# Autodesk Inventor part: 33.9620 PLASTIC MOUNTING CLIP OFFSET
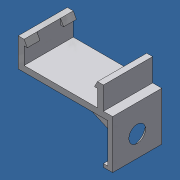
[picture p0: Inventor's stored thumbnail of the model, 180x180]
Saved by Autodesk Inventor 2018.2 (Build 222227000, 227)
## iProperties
Created: 2018-05
Part Number: 33.9620 PLASTIC MOUNTING CLIP OFFSET
Material: Generic
Document SubType Name: Modeling
Designer: amoles
Density: 1 g/cm^3
Appearance: White
Author: amoles
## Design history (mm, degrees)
sketch "Sketch1"
  geometry: L1 (-11.2, 8.75)-(-13, 8.75); L2 (-13, 8.75)-(-13, 0); L3 (-13, 0)-(13, 0); L4 (13, 0)-(13, 8.75); L5 (13, 8.75)-(11.2, 8.75); L6 (11.2, 8.75)-(11.2, 1.8); L7 (11.2, 1.8)-(-11.2, 1.8); L8 (-11.2, 1.8)-(-11.2, 8.75); 2 further points
  constraints: 16 end point, 6 perpendicular, 2 coincident, 1 horizontal, 1 horizontal alignment, 1 midpoint, 1 parallel
  dimensions: "d0" = 1.8 distance of L4.end L5.end; "d1" = 1.8 distance of L1.start L1.end; "d2" = 1.8 distance between parallel lines of L3 L7; "d3" = 8.75 distance of L3.end L4.end; "d4" = 26 distance of L2.end L3.end
extrude "Extrusion1" new body sketch "Sketch1" stored distance "d5" = 15; taper "d6" = 0 deg
sketch "Sketch3"
  geometry: L1 (-13, 8.75)-(-13, 0) reference; L2 (-11.2, 1.8)-(-11.2, 8.75) reference; L3 (-11.2, 8.75)-(-10.25, 6.95); L4 (-10.25, 6.95)-(-11.2, 6.95); L5 (-11.2, 6.95)-(-11.2, 8.75); 1 further point
  constraints: 6 end point, 1 collinear, 1 horizontal, 1 point on line
  dimensions: "d14" = 1.8 distance of L4.end L2.end; "d15" = 2.75 distance from line of L3.end L1
extrude "Extrusion2" join sketch "Sketch3" distance "d16" = 3.9; taper "d17" = 0 deg
mirror "Mirror1"
mirror "Mirror2"
sketch "Sketch4"
  geometry: L1 (0, 0)-(0, 8.75) reference; L2 (15, 0)-(0, 0) reference; L3 (15, 8.75)-(15, 0) reference; L4 (15, 1.8)-(0, 1.8) reference; 1 further point
extrude "Extrusion3" join sketch "Sketch4" distance "d18" = 2.8; taper "d19" = 0 deg
sketch "Sketch5"
  geometry: L1 (0, 15)-(28.8, 15) reference; L2 (28.8, 15)-(28.8, 0) reference; L3 (28.8, 0)-(27.35, 0); L4 (27.35, 0)-(27.35, 15); L5 (27.35, 15)-(28.8, 15); L6 (28.8, 15)-(28.8, 0); 1 further point
  constraints: 8 end point, 2 parallel, 1 horizontal, 1 perpendicular, 1 point on line
  dimensions: "d20" = 1.45 distance between parallel lines of L4 L2
extrude "Extrusion4" join sketch "Sketch5" distance "d21" = 13; taper "d22" = 0 deg
sketch "Sketch6"
  geometry: L1 (0, 0)-(0, -13) reference; L2 (15, -13)-(0, -13) reference; L3 (15, -13)-(0, -13); L4 (0, -13)-(0, -12); L5 (0, -12)-(15, -12); L6 (15, -12)-(15, -13); 1 further point
  constraints: 8 end point, 2 parallel, 1 horizontal, 1 perpendicular, 1 point on line
  dimensions: "d23" = 1 distance between parallel lines of L5 L2
extrude "Extrusion5" join sketch "Sketch6" distance "d24" = 1.35; taper "d25" = 0 deg
sketch "Sketch7"
  geometry: L1 (0, 0)-(15, 0) reference; L2 (0, -13)-(15, -13) reference; 3 further points
  constraints: 1 midpoint, 1 vertical alignment
  dimensions: "d26" = 6.5 distance from line of point (7.5, -6.5) L2
hole "Hole2" sketch "Sketch7" at (7.5, -6.5) diameter "d27" = 4.5; stored, may be unused: countersink angle "d31" = 90 deg, drill point angle "d33" = 118 deg; dims "d28" = 6, "d29" = 8, "d30" = 2, "d32" = 8
sketch "Sketch8"
  geometry: L1 (-14.35, 0)-(-14.35, -12) reference; L2 (13, 0)-(-14.35, 0) reference; L3 (-3.05, 0)-(-14.35, -5); 1 further point
  constraints: 2 end point, 2 point on line
  dimensions: "d34" = 11.3 distance from line of L3.start L1; "d35" = 5 distance from line of L2 L3.end
extrude "Extrusion6" join sketch "Sketch8" distance "d36" = 15; taper "d37" = 0 deg
sketch "Sketch9"
  geometry: L1 (16.05, 0)-(16.05, 15) reference; L2 (27.35, 15)-(27.35, 11.208) reference; L3 (16.05, 15)-(27.35, 15); L4 (27.35, 15)-(27.35, 13); L5 (27.35, 13)-(16.05, 13); L6 (16.05, 13)-(16.05, 15); L7 (27.35, 0)-(16.05, 0) reference; L8 (16.05, 0)-(27.35, 0); L9 (27.35, 0)-(27.35, 2); L10 (27.35, 2)-(16.05, 2); L11 (16.05, 2)-(16.05, 0); L12 (28.8, 0)-(28.8, 15) reference; L13 (16.05, 11.85)-(28.8, 11.85); L14 (28.8, 11.85)-(28.8, 3.15); L15 (28.8, 3.15)-(16.05, 3.15); L16 (16.05, 3.15)-(16.05, 11.85); L17 (27.35, 11.85)-(27.35, 3.15); 3 further points
  constraints: 26 end point, 7 point on line, 6 parallel, 3 horizontal, 3 perpendicular, 2 midpoint, 1 coincident
  dimensions: "d38" = 2 distance between parallel lines of L5 L3; "d39" = 2 distance between parallel lines of L10 L8; "d40" = 0 distance between parallel lines of L14 L12; "d41" = 1.15 distance between parallel lines of L5 L13
extrude "Extrusion7" cut sketch "Sketch9" distance "d42" = 5; taper "d43" = 0 deg
body "Solid1"
